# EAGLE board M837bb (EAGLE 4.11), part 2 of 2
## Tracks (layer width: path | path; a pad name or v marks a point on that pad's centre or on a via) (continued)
N$57  (via drill 0.61)
  Top 0.254: v24.13,53.34 26.67,55.88 v115.57,55.88 | v115.57,114.3 E32.12 | v115.57,109.22 E27.5 125.73,109.22 127,110.49 132.08,110.49 132.08,115.57 130.81,116.84 E27.13
  Bottom 0.254: v24.13,53.34 24.13,48.26 E45.3 | v115.57,55.88 119.38,59.69 119.38,107.95 120.65,109.22 E27.5 | v115.57,109.22 v115.57,114.3 | E29.9 128.27,172.72 125.73,170.18 125.73,119.38 128.27,116.84 E27.13
N$58
  Bottom 0.254: E27.6 123.19,106.68 124.46,107.95 124.46,151.13 123.19,152.4 E28.1
N$59
  Bottom 0.254: E27.4 120.65,111.76 119.38,113.03 119.38,140.97 120.65,142.24 E28.5
N$60  (via drill 0.61)
  Top 0.254: 242.57,104.14 243.84,105.41 256.54,105.41 257.81,106.68 E3.11 | v241.3,102.87 242.57,104.14 | E6.14 v238.76,48.26 | v210.82,111.76 212.09,110.49 236.22,110.49 242.57,104.14
  Bottom 0.254: v238.76,48.26 241.3,50.8 v241.3,102.87 | v210.82,111.76 210.82,142.24 209.55,143.51 209.55,177.8 207.01,180.34 E15.14
N$61
  Bottom 0.254: E17.8 171.45,71.12 170.18,72.39 170.18,113.03 171.45,114.3 E18.12
N$62
  Top 0.254: E24.6 E24.9
N$63
  Top 0.254: E23.4 140.97,144.78 138.43,147.32 134.62,147.32 133.35,148.59 133.35,153.67 167.64,153.67 171.45,149.86 E19.13
N$64
  Top 0.254: E23.6 146.05,139.7 147.32,140.97 170.18,140.97 171.45,139.7 E19.9
N$65  (via drill 0.61)
  Top 0.254: v158.75,142.24 E23.10
  Bottom 0.254: v158.75,142.24 158.75,104.14 163.83,99.06 163.83,86.36 E17.1
N$66  (via drill 0.61)
  Top 0.254: v133.35,143.51 144.78,143.51 146.05,144.78 E23.11 | v133.35,171.45 124.46,171.45 123.19,172.72 E29.6
  Bottom 0.254: v133.35,143.51 v133.35,171.45
N$67  (via drill 0.61)
  Top 0.254: v118.11,111.76 119.38,113.03 127,113.03 128.27,114.3 E27.12
  Bottom 0.254: v118.11,111.76 118.11,115.57 116.84,116.84 116.84,179.07 120.65,182.88 E29.2
N$68
  Top 0.254: E46.3 31.75,81.28 35.56,77.47 83.82,77.47 85.09,78.74 E36.11
N$69  (via drill 0.61)
  Top 0.254: E43.9 57.15,139.7 58.42,140.97 v133.35,140.97 144.78,140.97 147.32,143.51 170.18,143.51 171.45,144.78 E19.11 | v135.89,77.47 162.56,77.47 163.83,78.74 E17.4
  Bottom 0.254: v135.89,77.47 134.62,78.74 134.62,115.57 133.35,116.84 v133.35,140.97
N$70  (via drill 0.61)
  Top 0.254: v193.04,111.76 187.96,106.68 E18.9 | v125.73,19.05 127,19.05 127,13.97 EDGE.CA1 | v124.46,64.77 125.73,66.04 167.64,66.04 170.18,68.58 170.18,73.66 E17.9
  Bottom 0.254: E17.9 173.99,73.66 175.26,74.93 175.26,105.41 173.99,106.68 E18.9 | v193.04,111.76 193.04,138.43 196.85,142.24 E14.5 | v125.73,19.05 124.46,20.32 v124.46,64.77
N$71  (via drill 0.61)
  Top 0.254: v212.09,161.29 v46.99,161.29
  Bottom 0.254: v212.09,161.29 212.09,111.76 209.55,109.22 209.55,73.66 207.01,71.12 E12.8 | v46.99,161.29 46.99,175.26 49.53,177.8 E44.4
N$72
  Bottom 0.254: E43.1 48.26,171.45 49.53,172.72 E44.6
N$73
  Bottom 0.254: E44.8 58.42,148.59 57.15,147.32 E43.12
N$74  (via drill 0.61)
  Top 0.254: v208.28,149.86 219.71,149.86 224.79,144.78 E9.4
  Bottom 0.254: v208.28,149.86 208.28,160.02 200.66,167.64 200.66,179.07 199.39,180.34 E15.3
N$75  (via drill 0.61)
  Top 0.254: v223.52,179.07 200.66,179.07 199.39,177.8 E15.4
  Bottom 0.254: v223.52,179.07 223.52,153.67 224.79,152.4 E9.1
N$76  (via drill 0.61)
  Top 0.254: v210.82,152.4 212.09,151.13 231.14,151.13 232.41,149.86 E9.13
  Bottom 0.254: v210.82,152.4 210.82,181.61 203.2,181.61 203.2,176.53 204.47,175.26 E15.12
N$77  (via drill 0.61)
  Top 0.254: v213.36,143.51 231.14,143.51 232.41,142.24 E9.10 | v213.36,173.99 209.55,177.8 E15.13
  Bottom 0.254: v213.36,143.51 v213.36,173.99
N$78
  Bottom 0.254: E8.2 227.33,116.84 228.6,118.11 228.6,140.97 227.33,142.24 E9.5
N$79  (via drill 0.61)
  Top 0.254: v222.25,181.61 256.54,181.61 257.81,182.88 E5.13
  Bottom 0.254: 224.79,149.86 223.52,148.59 223.52,115.57 224.79,114.3 E8.3 | v222.25,181.61 222.25,152.4 224.79,149.86 | 224.79,149.86 E9.2
N$80
  Top 0.254: E4.2 250.19,149.86 247.65,147.32 E9.12
  Bottom 0.254: E8.13 234.95,116.84 237.49,119.38 237.49,144.78 234.95,147.32 E9.12
N$81
  Top 0.254: E4.5 250.19,142.24 247.65,139.7 E9.9
  Bottom 0.254: E8.14 234.95,119.38 236.22,120.65 236.22,138.43 234.95,139.7 E9.9
N$82  (via drill 0.61)
  Top 0.254: v237.49,146.05 236.22,146.05 234.95,144.78 E9.11
  Bottom 0.254: v237.49,146.05 237.49,185.42 236.22,186.69 231.14,186.69 231.14,184.15 232.41,182.88 E10.15
N$83
  Bottom 0.254: E9.3 227.33,147.32 228.6,148.59 228.6,181.61 227.33,182.88 E10.2
N$84
  Bottom 0.254: E9.8 232.41,137.16 231.14,138.43 231.14,179.07 232.41,180.34 E10.14
N$86  (via drill 0.61)
  Top 0.254: v261.62,146.05 254,146.05 252.73,144.78 E4.4
  Bottom 0.254: E4.4 250.19,144.78 248.92,146.05 248.92,179.07 250.19,180.34 E5.3 | v261.62,146.05 261.62,115.57 260.35,114.3 E3.14
N$87  (via drill 0.61)
  Top 0.254: v262.89,149.86 261.62,151.13 254,151.13 252.73,152.4 E4.1
  Bottom 0.254: E4.1 252.73,152.4 254,153.67 254,171.45 252.73,172.72 E5.6 | v262.89,149.86 262.89,113.03 256.54,113.03 256.54,115.57 257.81,116.84 E3.15
N$88
  Top 0.254: E10.7 227.33,170.18 228.6,171.45 255.27,171.45 256.54,172.72 E5.9
N$89
  Top 0.254: E10.9 234.95,167.64 236.22,168.91 254,168.91 256.54,171.45 261.62,171.45 261.62,173.99 254,173.99 252.73,175.26 E5.5
N$90  (via drill 0.61)
  Top 0.254: v247.65,180.34 242.57,180.34 234.95,172.72 E10.11
  Bottom 0.254: v247.65,180.34 250.19,182.88 E5.2
N$93  (via drill 0.61)
  Top 0.254: E3.2 v256.54,116.84
  Bottom 0.254: v256.54,116.84 256.54,128.27 255.27,129.54 255.27,167.64 256.54,168.91 | 256.54,168.91 257.81,170.18 E5.8 | 256.54,168.91 256.54,179.07 257.81,180.34 E5.12
N$94  (via drill 0.61)
  Top 0.254: 257.81,139.7 257.81,142.24 E4.10 | v246.38,74.93 203.2,74.93 201.93,73.66 E12.6 | 257.81,139.7 256.54,138.43 v247.65,138.43 | 257.81,139.7 E4.9
  Bottom 0.254: v246.38,74.93 247.65,76.2 247.65,111.76 | 247.65,111.76 250.19,114.3 E3.3 | 247.65,111.76 v247.65,138.43
N$95  (via drill 0.61)
  Top 0.254: v246.38,85.09 248.92,85.09 250.19,83.82 E2.2 | v187.96,16.51 187.96,13.97 EDGE.BB1 | v193.04,48.26 194.31,49.53 210.82,49.53 218.44,57.15 v245.11,57.15
  Bottom 0.254: E5.11 260.35,177.8 261.62,179.07 261.62,186.69 248.92,186.69 246.38,184.15 v246.38,85.09 245.11,83.82 v245.11,57.15 | v187.96,16.51 186.69,17.78 186.69,33.02 193.04,39.37 v193.04,48.26
N$96  (via drill 0.61)
  Top 0.254: v261.62,15.24 261.62,13.97 EDGE.AA1 | v262.89,81.28 264.16,81.28 264.16,146.05 261.62,148.59 254,148.59 252.73,147.32 E4.3
  Bottom 0.254: v261.62,15.24 261.62,17.78 262.89,19.05 v262.89,81.28 260.35,83.82 E2.15
N$100  (via drill 0.61)
  Top 0.254: v248.92,115.57 262.89,115.57 262.89,83.82 260.35,81.28 E2.14 257.81,81.28 256.54,80.01 v243.84,80.01 | v243.84,27.94 257.81,13.97 EDGE.AB1
  Bottom 0.254: v248.92,115.57 248.92,138.43 250.19,139.7 E4.6 | v243.84,27.94 v243.84,80.01
N$101  (via drill 0.61)
  Top 0.254: 255.27,87.63 v255.27,88.9 | 255.27,87.63 255.27,83.82 252.73,81.28 E2.3 | v255.27,128.27 255.27,137.16 E4.8 | v191.77,16.51 191.77,13.97 EDGE.BA1 | v199.39,29.21 200.66,30.48 v217.17,30.48 | v217.17,86.36 218.44,87.63 255.27,87.63
  Bottom 0.254: v255.27,88.9 v255.27,128.27 | v191.77,16.51 191.77,21.59 v199.39,29.21 | v217.17,86.36 v217.17,30.48
N$102
  Top 0.254: E6.6 227.33,40.64 231.14,44.45 242.57,44.45 247.65,49.53 261.62,49.53 261.62,54.61 254,54.61 252.73,53.34 E1.1
  Bottom 0.254: E2.7 250.19,71.12 248.92,69.85 248.92,54.61 250.19,53.34 E1.1
N$103  (via drill 0.61)
  Top 0.254: 241.3,41.91 242.57,40.64 E1.6 | v240.03,43.18 241.3,41.91 | 241.3,41.91 246.38,46.99 262.89,46.99 262.89,54.61 261.62,55.88 260.35,55.88 260.35,68.58 E2.9
  Bottom 0.254: v240.03,43.18 234.95,38.1 E6.10
N$104  (via drill 0.61)
  Top 0.254: v256.54,52.07 246.38,52.07 245.11,50.8 E6.15
  Bottom 0.254: E1.10 257.81,38.1 256.54,39.37 v256.54,52.07 256.54,72.39 257.81,73.66 E2.11
N$105  (via drill 0.61)
  Top 0.254: v229.87,41.91 240.03,41.91 242.57,39.37 256.54,39.37 257.81,40.64 E1.11 | v229.87,157.48 227.33,160.02 v38.1,160.02
  Bottom 0.254: 35.56,160.02 35.56,168.91 36.83,170.18 E48.8 | 35.56,160.02 35.56,148.59 36.83,147.32 E47.14 | v229.87,41.91 v229.87,157.48 | v38.1,160.02 35.56,160.02
N$106  (via drill 0.61)
  Top 0.254: v264.16,44.45 254,44.45 252.73,43.18 E1.5 | v27.94,151.13 35.56,151.13 36.83,149.86 E47.15
  Bottom 0.254: v264.16,44.45 264.16,186.69 255.27,195.58 33.02,195.58 33.02,173.99 31.75,172.72 E48.6 29.21,172.72 27.94,171.45 v27.94,151.13
N$107  (via drill 0.61)
  Top 0.254: v212.09,49.53 245.11,49.53 246.38,50.8 E1.2 | v210.82,88.9 168.91,88.9 167.64,90.17 109.22,90.17 105.41,93.98 58.42,93.98 50.8,101.6 44.45,101.6 43.18,102.87 43.18,110.49 v27.94,110.49 20.32,110.49 19.05,111.76 E52.11
  Bottom 0.254: v212.09,49.53 210.82,50.8 v210.82,88.9 | v27.94,110.49 27.94,148.59 29.21,149.86 E47.2
N$110  (via drill 0.61)
  Top 0.254: v25.4,107.95 27.94,105.41 35.56,105.41 36.83,104.14 E49.10
  Bottom 0.254: v25.4,107.95 25.4,146.05 20.32,151.13 13.97,151.13 13.97,170.18 11.43,172.72 E54.6
N$113  (via drill 0.61)
  Top 0.254: v237.49,80.01 236.22,81.28 E7.12 229.87,81.28 227.33,83.82 E7.2 | E7.9 v237.49,73.66 | v243.84,143.51 256.54,143.51 257.81,144.78 E4.11
  Bottom 0.254: v237.49,73.66 v237.49,80.01 238.76,81.28 238.76,138.43 v243.84,143.51
N$118  (via drill 0.61)
  Top 0.254: v7.62,39.37 15.24,39.37 16.51,38.1 E50.10 | v3.81,90.17 12.7,99.06 v26.67,99.06 v34.29,99.06 | v3.81,64.77 111.76,64.77 114.3,62.23 224.79,62.23 232.41,69.85 261.62,69.85 261.62,72.39 256.54,72.39 256.54,74.93 254,77.47 248.92,77.47 247.65,78.74 E7.11
  Bottom 0.254: v7.62,39.37 3.81,43.18 v3.81,64.77 v3.81,90.17 | v34.29,99.06 36.83,101.6 E49.9 | v26.67,99.06 26.67,172.72 29.21,175.26 E48.5
N$119  (via drill 0.61)
  Top 0.254: v26.67,50.8 E50.15 | v26.67,66.04 111.76,66.04 114.3,63.5 224.79,63.5 232.41,71.12 E7.8
  Bottom 0.254: v26.67,50.8 v26.67,66.04 26.67,97.79 27.94,99.06 27.94,105.41 34.29,105.41 | 34.29,105.41 36.83,105.41 36.83,106.68 E49.11 | 34.29,105.41 34.29,170.18 36.83,172.72 E48.9
N$120
  Bottom 0.254: E51.2 11.43,83.82 12.7,85.09 12.7,107.95 11.43,109.22 E52.5
N$121  (via drill 0.61)
  Top 0.254: v6.35,93.98 15.24,102.87 27.94,102.87 | 27.94,102.87 29.21,104.14 E49.7 31.75,104.14 35.56,100.33 50.8,100.33 62.23,88.9 167.64,88.9 168.91,87.63 175.26,87.63 177.8,85.09 220.98,85.09 224.79,81.28 E7.3 | 27.94,102.87 22.86,107.95 15.24,107.95 15.24,113.03 16.51,114.3 E52.12
  Bottom 0.254: E52.12 16.51,114.3 16.51,116.84 E52.13 | v6.35,93.98 6.35,43.18 8.89,40.64 E50.6
N$122
  Top 0.254: E51.13 16.51,83.82 11.43,88.9 3.81,88.9 2.54,90.17 2.54,116.84 E52.2
N$124
  Bottom 0.254: E51.14 16.51,86.36 15.24,87.63 15.24,105.41 16.51,106.68 E52.9
N$126  (via drill 0.61)
  Top 0.254: v6.35,121.92 8.89,119.38 E52.1 | v6.35,143.51 7.62,144.78 E53.4
  Bottom 0.254: v6.35,121.92 v6.35,143.51
N$128  (via drill 0.61)
  Top 0.254: v22.86,49.53 20.32,49.53 19.05,48.26 E50.14 | v22.86,72.39 v21.59,73.66 | E47.11 36.83,139.7 35.56,140.97 21.59,140.97 20.32,139.7 E53.11
  Bottom 0.254: v22.86,49.53 v22.86,72.39 | v21.59,73.66 21.59,137.16 19.05,139.7 E53.11
N$129  (via drill 0.61)
  Top 0.254: v6.35,41.91 12.7,41.91 13.97,40.64 E50.11 | v5.08,142.24 E53.5 | v5.08,133.35 35.56,133.35 36.83,134.62 E47.9
  Bottom 0.254: v6.35,41.91 5.08,43.18 v5.08,133.35 v5.08,142.24
N$130  (via drill 0.61)
  Top 0.254: v7.62,138.43 27.94,138.43 29.21,137.16 E47.7
  Bottom 0.254: E50.5 8.89,43.18 7.62,44.45 v7.62,138.43 7.62,148.59 8.89,149.86 E53.2
N$135
  Bottom 0.254: E52.10 16.51,109.22 15.24,110.49 15.24,140.97 16.51,142.24 E53.12
N$137  (via drill 0.61)
  Top 0.254: v209.55,123.19 210.82,121.92 247.65,121.92 250.19,119.38 E3.1
  Bottom 0.254: v209.55,123.19 209.55,142.24 207.01,144.78 E14.11
N$140
  Bottom 0.254: E52.4 11.43,111.76 12.7,113.03 12.7,146.05 11.43,147.32 E53.3
N$141  (via drill 0.61)
  Top 0.254: v20.32,111.76 21.59,113.03 35.56,113.03 36.83,114.3 E49.14
  Bottom 0.254: v20.32,111.76 20.32,105.41 19.05,104.14 E52.8
N$142
  Top 0.254: E52.3 11.43,114.3 12.7,115.57 35.56,115.57 36.83,116.84 E49.15
N$143  (via drill 0.61)
  Top 0.254: v24.13,105.41 12.7,105.41 11.43,106.68 E52.6 | v24.13,116.84 E49.2
  Bottom 0.254: v24.13,105.41 v24.13,116.84
N$145  (via drill 0.61)
  Top 0.254: R8.1 22.86,69.85 v1.27,69.85 1.27,58.42 8.89,50.8 E50.2 | v3.81,138.43 2.54,138.43 2.54,139.7 3.81,140.97 20.32,140.97 20.32,144.78 27.94,152.4 E47.1
  Bottom 0.254: v3.81,138.43 3.81,91.44 1.27,88.9 v1.27,69.85
POWER_OK  (via drill 0.61)
  Top 0.254: v187.96,19.05 185.42,19.05 184.15,17.78 v140.97,17.78
  Bottom 0.254: v187.96,19.05 187.96,29.21 196.85,38.1 E11.7 | v140.97,17.78 138.43,15.24 138.43,13.97 EDGE.BV2
POWER_OK\  (via drill 0.61)
  Top 0.254: v184.15,49.53 185.42,50.8 E11.2
  Bottom 0.254: v184.15,49.53 184.15,40.64 E16.9
RDF\
  Top 0.254: E4.12 261.62,147.32 262.89,146.05 262.89,118.11 177.8,118.11 175.26,115.57 157.48,115.57 151.13,109.22 E22.12
  Bottom 0.254: E4.12 257.81,147.32 257.81,149.86 E4.13 | E21.9 151.13,73.66 152.4,74.93 152.4,107.95 151.13,109.22 E22.12
RIB\
  Top 0.254: E18.5 163.83,109.22 158.75,104.14 E22.10
  Bottom 0.254: E21.11 148.59,78.74 147.32,80.01 147.32,102.87 148.59,104.14 E22.10
RIF\
  Top 0.254: E18.2 156.21,116.84 152.4,113.03 147.32,113.03 147.32,106.68 E22.11
  Bottom 0.254: E21.10 148.59,76.2 146.05,78.74 146.05,104.14 148.59,106.68 E22.11
RMF\  (via drill 0.61)
  Top 0.254: v2.54,135.89 15.24,135.89 16.51,134.62 E53.9 | v146.05,173.99 144.78,173.99 143.51,175.26 E24.5 | E15.9 203.2,167.64 201.93,166.37 v157.48,166.37 147.32,166.37 v146.05,167.64 143.51,165.1 v10.16,165.1 | v157.48,101.6 E22.9
  Bottom 0.254: 2.54,165.1 2.54,171.45 7.62,176.53 | 2.54,165.1 v2.54,135.89 | 7.62,176.53 8.89,177.8 E54.4 | 7.62,176.53 7.62,184.15 8.89,185.42 E54.1 | v146.05,167.64 v146.05,173.99 | v157.48,101.6 v157.48,166.37 | v10.16,165.1 2.54,165.1
RTF\  (via drill 0.61)
  Top 0.254: v144.78,171.45 139.7,171.45 138.43,170.18 E29.8 | E24.4 v138.43,177.8
  Bottom 0.254: v144.78,171.45 144.78,176.53 143.51,177.8 E24.4 | v138.43,177.8 138.43,181.61 135.89,184.15 135.89,194.31 50.8,194.31 44.45,187.96 44.45,182.88 E48.13
RUN\  (via drill 0.61)
  Top 0.254: v140.97,16.51 v146.05,16.51
  Bottom 0.254: v146.05,16.51 146.05,49.53 156.21,49.53 161.29,44.45 161.29,41.91 167.64,41.91 171.45,38.1 E16.8 | v140.97,16.51 140.97,13.97 EDGE.BU2
SINT\
  Bottom 0.254: 140.97,182.88 139.7,181.61 139.7,115.57 140.97,114.3 E22.3 | 140.97,182.88 140.97,185.42 E24.1 | 140.97,182.88 E24.2
SKIP\  (via drill 0.61)
  Top 0.254: v82.55,15.24 82.55,13.97 EDGE.CS1
  Bottom 0.254: v82.55,15.24 82.55,44.45 83.82,45.72 83.82,49.53 85.09,50.8 E35.13
SUF\
  Bottom 0.254: E22.5 143.51,109.22 144.78,110.49 144.78,146.05 143.51,147.32 E23.3
TP2  (via drill 0.61)
  Top 0.254: v118.11,38.1 E25.7
  Bottom 0.254: v118.11,38.1 115.57,35.56 115.57,13.97 EDGE.CE2
TP2H  (via drill 0.61)
  Top 0.254: v115.57,39.37 53.34,39.37 52.07,38.1 E40.7 | v53.34,134.62 62.23,125.73 v63.5,125.73
  Bottom 0.254: v115.57,39.37 118.11,41.91 118.11,48.26 120.65,50.8 E25.2 | v53.34,134.62 52.07,135.89 52.07,152.4 55.88,156.21 55.88,179.07 57.15,180.34 E44.12 | v63.5,125.73 63.5,52.07 60.96,49.53 55.88,49.53 55.88,41.91 52.07,38.1 E40.7
TP3
  Bottom 0.254: E30.7 100.33,38.1 100.33,20.32 104.14,16.51 105.41,16.51 105.41,22.86 106.68,24.13 107.95,24.13 107.95,13.97 EDGE.CH2
TP3H  (via drill 0.61)
  Top 0.254: E44.5 E44.10 78.74,175.26 80.01,176.53 101.6,176.53 104.14,179.07 109.22,179.07 113.03,182.88 118.11,182.88 119.38,184.15 144.78,184.15 147.32,181.61 166.37,181.61 166.37,176.53 165.1,175.26 E24.10 | v74.93,52.07 96.52,52.07 97.79,50.8 E30.2 | v50.8,143.51 60.96,143.51 62.23,144.78 E39.4
  Bottom 0.254: 170.18,146.05 170.18,143.51 171.45,142.24 E19.10 | 170.18,146.05 171.45,147.32 E19.12 | 170.18,146.05 170.18,156.21 163.83,162.56 163.83,175.26 E24.10 | v74.93,52.07 74.93,170.18 60.96,184.15 53.34,184.15 | 53.34,184.15 52.07,184.15 52.07,182.88 E44.2 | v50.8,143.51 50.8,166.37 53.34,168.91 53.34,175.26 | 53.34,175.26 53.34,184.15 | E44.5 53.34,175.26
TP4  (via drill 0.61)
  Top 0.254: v168.91,43.18 166.37,40.64 E16.6 | E17.11 v176.53,78.74 v185.42,78.74 | v187.96,114.3 E13.3 | v106.68,22.86 114.3,30.48 144.78,30.48 147.32,33.02 v168.91,33.02
  Bottom 0.254: v168.91,43.18 168.91,45.72 170.18,46.99 | 170.18,46.99 171.45,48.26 E16.12 | v176.53,78.74 176.53,66.04 170.18,59.69 170.18,46.99 | v187.96,114.3 185.42,111.76 v185.42,78.74 | v106.68,22.86 106.68,13.97 EDGE.CJ2 | v168.91,33.02 168.91,38.1 166.37,40.64 E16.6
TP_CB1  (via drill 0.61)
  Top 0.254: R6.1 E26.2 | v114.3,19.05 115.57,17.78 120.65,17.78 124.46,13.97 EDGE.CB1
  Bottom 0.254: E26.3 120.65,81.28 120.65,83.82 E26.2 | R6.1 115.57,76.2 114.3,74.93 v114.3,19.05
TS1\  (via drill 0.61)
  Top 0.254: v66.04,29.21 67.31,27.94 v90.17,27.94 | v182.88,124.46 177.8,129.54 v66.04,129.54
  Bottom 0.254: v66.04,29.21 v66.04,129.54 66.04,138.43 64.77,139.7 E39.6 | v90.17,27.94 101.6,16.51 101.6,13.97 EDGE.CK2 | v182.88,124.46 182.88,80.01 194.31,68.58 194.31,43.18 196.85,40.64 E11.6
TS_DISABLE\  (via drill 0.61)
  Top 0.762: v77.47,191.77 110.49,191.77 111.76,190.5 J1.2 | v176.53,121.92 171.45,127 v138.43,127 | v176.53,81.28 E12.3
  Bottom 0.762: v77.47,191.77 77.47,152.4 E38.1 | v176.53,81.28 v176.53,121.92 | v138.43,127 138.43,175.26 135.89,177.8 135.89,182.88 134.62,184.15 R5.1 134.62,190.5 J1.2
UF  (via drill 0.61)
  Top 0.254: E35.6 77.47,40.64 77.47,43.18 E35.5 | E2.5 248.92,76.2 247.65,77.47 228.6,77.47 227.33,76.2 E7.5 215.9,76.2 v208.28,83.82 | v83.82,97.79 85.09,99.06 143.51,99.06 144.78,97.79 v204.47,97.79
  Bottom 0.254: v83.82,97.79 83.82,85.09 82.55,83.82 82.55,45.72 80.01,43.18 E35.5 | v204.47,97.79 208.28,93.98 v208.28,83.82
USER_MODE\  (via drill 0.61)
  Top 0.254: v30.48,20.32 33.02,22.86 v68.58,22.86
  Bottom 0.254: 76.2,46.99 77.47,45.72 E35.4 | 76.2,46.99 76.2,110.49 77.47,111.76 E37.4 | v30.48,20.32 30.48,17.78 26.67,13.97 EDGE.DM2 | v68.58,22.86 76.2,30.48 76.2,46.99
VCC  (via drill 0.61)
  Top 0.762: v134.62,180.34 C30.1 | 127,186.69 109.22,186.69 107.95,185.42 E34.14 | 127,186.69 128.27,185.42 E29.14 | 127,186.69 147.32,186.69 148.59,185.42 E24.14 | C54.1 19.05,187.96 R7.2 44.45,189.23 55.88,189.23 | 55.88,189.23 C44.1 | 16.51,149.86 16.51,147.32 E53.14 | 16.51,149.86 16.51,152.4 E53.16 19.05,152.4 20.32,153.67 36.83,153.67 | 16.51,149.86 E53.15 | 36.83,153.67 36.83,152.4 E47.16 39.37,152.4 40.64,153.67 54.61,153.67 | 36.83,153.67 C48.1 | 54.61,153.67 54.61,152.4 E43.14 | 54.61,156.21 54.61,153.67 | 54.61,156.21 C43.1 | 54.61,156.21 68.58,156.21 C39.1 71.12,156.21 83.82,156.21 C38.1 105.41,157.48 105.41,156.21 | C34.1 104.14,189.23 55.88,189.23 | C52.1 16.51,119.38 E52.14 19.05,119.38 20.32,118.11 35.56,118.11 36.83,119.38 E49.16 | 46.99,134.62 C47.1 | 46.99,134.62 48.26,135.89 68.58,135.89 69.85,137.16 E39.8 | C42.1 46.99,134.62 | 88.9,120.65 87.63,119.38 E37.14 | 88.9,120.65 104.14,120.65 105.41,119.38 E32.14 | 147.32,123.19 129.54,123.19 C28.1 127,125.73 106.68,125.73 C33.1 | C23.1 147.32,123.19 | C20.1 170.18,123.19 147.32,123.19 | 88.9,120.65 60.96,120.65 59.69,119.38 E42.14 | 257.81,186.69 257.81,185.42 E5.14 | 257.81,186.69 C6.1 | C16.1 204.47,185.42 E15.16 207.01,185.42 208.28,186.69 232.41,186.69 | 232.41,186.69 232.41,185.42 E10.16 | 232.41,186.69 C11.1 | 232.41,186.69 257.81,186.69 | 257.81,153.67 257.81,152.4 E4.14 | 257.81,153.67 C5.1 | 232.41,153.67 232.41,152.4 E9.14 | 232.41,153.67 C10.1 | 232.41,153.67 208.28,153.67 207.01,152.4 E14.14 | 232.41,153.67 257.81,153.67 | 105.41,156.21 105.41,152.4 E33.14 | 127,156.21 C29.1 | 105.41,156.21 127,156.21 | 147.32,156.21 C24.1 | 127,156.21 147.32,156.21
  Top 0.762: 170.18,156.21 C21.1 | 147.32,156.21 170.18,156.21 | C15.1 203.2,156.21 170.18,156.21 | C51.1 17.78,92.71 v24.13,92.71 35.56,92.71 | C46.1 35.56,92.71 | C41.1 55.88,92.71 35.56,92.71 | v90.17,53.34 E35.14 | C31.1 104.14,59.69 58.42,59.69 | C40.1 58.42,59.69 | 58.42,59.69 38.1,59.69 C45.1 35.56,57.15 17.78,57.15 C50.1 | E36.8 85.09,71.12 83.82,69.85 60.96,69.85 59.69,71.12 E41.8 | E45.8 39.37,38.1 40.64,36.83 55.88,36.83 57.15,38.1 E40.8 59.69,38.1 60.96,36.83 v92.71,36.83 109.22,36.83 | 109.22,36.83 107.95,38.1 E30.8 | 127,36.83 109.22,36.83 | 127,36.83 128.27,38.1 E25.8 C26.1 | 127,36.83 147.32,36.83 148.59,38.1 E20.8 151.13,38.1 152.4,36.83 181.61,36.83 C17.1 191.77,39.37 203.2,39.37 204.47,38.1 E11.8 | E3.16 257.81,119.38 C4.1 256.54,125.73 233.68,125.73 C9.1 231.14,123.19 223.52,123.19 | 231.14,92.71 205.74,92.71 C13.1 203.2,92.71 198.12,92.71 196.85,91.44 C19.1 | 231.14,92.71 C8.1 | C3.1 256.54,92.71 231.14,92.71 | 223.52,123.19 212.09,123.19 210.82,124.46 C14.1 | E17.14 168.91,86.36 167.64,87.63 158.75,87.63 R2.2 E21.14 148.59,86.36 147.32,87.63 127,87.63 | C36.1 86.36,90.17 104.14,90.17 C32.1 | 128.27,93.98 R4.2 | 128.27,93.98 R6.2 | C27.1 128.27,93.98 | 127,87.63 109.22,87.63 107.95,86.36 E31.14 | 127,87.63 128.27,86.36 E26.14 | E1.15 257.81,50.8 257.81,53.34 E1.16 | C2.1 256.54,58.42 252.73,54.61 236.22,54.61 234.95,53.34 E6.16 | R3.2 161.29,54.61 170.18,54.61 171.45,53.34 E16.14 R1.2 | C18.1 172.72,57.15 203.2,57.15 C12.1 219.71,58.42 220.98,59.69 231.14,59.69 C7.1 | v149.86,134.62 212.09,134.62 223.52,123.19
  Bottom 0.762: C25.1 148.59,185.42 E24.14 | C34.1 105.41,185.42 E34.14 | R5.2 v134.62,180.34 134.62,181.61 130.81,185.42 E29.14 | C44.1 57.15,185.42 E44.14 | 16.51,185.42 C54.1 | 36.83,187.96 36.83,185.42 E48.14 | 36.83,187.96 C49.1 | R7.2 36.83,187.96 | E53.16 16.51,152.4 C53.1 15.24,158.75 15.24,184.15 16.51,185.42 | 16.51,185.42 E54.14 | C42.1 57.15,119.38 E42.14 | C47.1 36.83,119.38 E49.16 | C37.1 85.09,119.38 E37.14 | E32.14 105.41,119.38 C33.1 109.22,128.27 109.22,151.13 107.95,152.4 E33.14 | C20.1 171.45,119.38 E18.14 | C28.1 128.27,119.38 E27.14 | E22.16 148.59,119.38 C23.1 149.86,125.73 v149.86,134.62 | C15.1 204.47,152.4 E14.14 | C21.1 171.45,152.4 E19.14 | C24.1 148.59,152.4 E23.14 | C29.1 128.27,152.4 E28.14 | C38.1 85.09,152.4 E38.14 | C10.1 236.22,161.29 236.22,184.15 234.95,185.42 E10.16 | v24.13,92.71 R8.2 | C35.1 92.71,34.29 v92.71,36.83 C58.1 90.17,48.26 v90.17,53.34 | E35.14 87.63,53.34 87.63,71.12 E36.8 | E50.16 16.51,53.34 C50.1 16.51,71.12 E51.8 | C45.1 36.83,71.12 | C40.1 57.15,71.12 E41.8 | C46.1 34.29,88.9 34.29,74.93 35.56,73.66 35.56,72.39 36.83,71.12 | 36.83,71.12 E46.8 | EDGE.CA2 127,13.97 C57.+ 127,26.67 128.27,27.94 128.27,38.1 E25.8 | C22.1 153.67,41.91 153.67,29.21 151.13,29.21 151.13,38.1 E20.8 | EDGE.AA2 260.35,13.97 260.35,20.32 256.54,24.13 C55.+ 256.54,30.48 C1.1 255.27,34.29 255.27,85.09 257.81,87.63 | 257.81,87.63 257.81,86.36 E2.16 | C3.1 257.81,87.63 | 204.47,119.38 C14.1 | E12.14 204.47,86.36 C13.1 203.2,92.71 203.2,118.11 204.47,119.38 | E7.14 232.41,86.36 C8.1 232.41,104.14 E8.8 | 204.47,119.38 E13.14 | C19.1 171.45,86.36 E17.14 | C32.1 105.41,86.36 E31.14 | C27.1 128.27,86.36 E26.14
  Bottom 0.762: 190.5,15.24 190.5,13.97 EDGE.BA2 | 190.5,15.24 C56.+ | C7.1 232.41,53.34 E6.16 | E1.14 257.81,48.26 257.81,50.8 E1.15 | C2.1 257.81,53.34 E1.16 | C18.1 171.45,53.34 E16.14 | C12.1 201.93,55.88 201.93,40.64 204.47,38.1 E11.8 | 190.5,15.24 185.42,15.24 185.42,33.02 187.96,35.56 C17.1 | R2.2 160.02,83.82 R3.2

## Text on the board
Bottom: M837 Memory Ext. and Time Share | VRS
